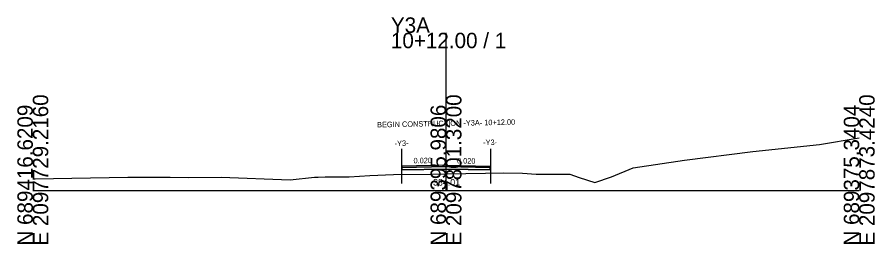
# Model space of a CAD drawing. Extents: x -26 to 2453, y -10 to 1032.
# Drawn here: x 1147.2 to 1302.8, y -9.7 to 31.5 of the extents above; entities that cross this region are included whole.
import ezdxf

# ---------------------------------------------------------------- set-up
doc = ezdxf.new("R2010")
doc.units = 0
for name, color, linetype in [('Exist Cross Section Cell', 7, 'Continuous'), ('Exist XS Center Line Elevation Label', 7, 'Continuous'), ('Exist XS Ground Line', 7, 'Continuous'), ('Prop CMT Pvmt Course 1', 7, 'Continuous'), ('Prop CMT Pvmt Course 2', 7, 'Continuous'), ('Prop CMT Pvmt Course 3', 7, 'Continuous'), ('Prop CMT Pvmt Surface', 7, 'Continuous'), ('Prop CMT Pvmt Surface Shoulder', 7, 'Continuous'), ('Prop CMT Shld Paved Course 1', 7, 'Continuous'), ('Prop CMT Shld Paved Course 2', 7, 'Continuous'), ('Prop CMT Shld Paved Course 3', 7, 'Continuous'), ('Prop CMT Subgrade Earthwork', 7, 'Continuous'), ('Prop XS SE Text', 7, 'Continuous')]:
    doc.layers.add(name, color=color, linetype=linetype)

msp = doc.modelspace()

# ---------------------------------------------------------------- linework, layer by layer
at = {"layer": 'Exist Cross Section Cell'}
for p, q in [((1225, 0), (1225, 28.68)), ((1150, 0), (1225, 0)), ((1225, 0), (1300, 0))]:
    msp.add_line(p, q, dxfattribs=at)
at = {"layer": 'Exist XS Center Line Elevation Label'}
for p, q in [((1216.9, 7.58), (1216.9, 4.45)), ((1233.1, 7.58), (1233.1, 4.45)), ((1216.9, 4.45), (1216.9, 1.31)), ((1233.1, 4.45), (1233.1, 1.31))]:
    msp.add_line(p, q, dxfattribs=at)
at = {"layer": 'Exist XS Ground Line'}
msp.add_lwpolyline([(1150, 2.1), (1150.44, 2.12), (1157.09, 2.26), (1167.25, 2.44), (1169.79, 2.42), (1174.96, 2.41), (1178.29, 2.4), (1184.17, 2.45), (1196.73, 1.97), (1201.13, 2.43), (1201.77, 2.44), (1203.07, 2.47), (1207.42, 2.52), (1211.15, 2.76), (1215.44, 2.89), (1222.42, 2.96), (1225, 3.01), (1232.19, 3.16), (1235.5, 3.2), (1238.91, 3.18), (1241.35, 3), (1247.5, 2.99), (1249.16, 2.35), (1252, 1.49), (1255.06, 2.51), (1258.96, 4.13), (1268.31, 5.52), (1280.68, 7.1), (1292.8, 8.39), (1300, 9.56)], dxfattribs=at)
at = {"layer": 'Prop CMT Pvmt Course 1'}
for points in [[(1225, 4.61), (1217, 4.45)], [(1217, 4.45), (1217, 4.2)], [(1217, 4.2), (1225, 4.36)], [(1225, 4.36), (1225, 4.61)], [(1225, 4.61), (1233, 4.45)], [(1225, 4.36), (1225, 4.61)], [(1225, 4.36), (1225, 4.61)], [(1233, 4.2), (1225, 4.36)], [(1233, 4.45), (1233, 4.2)]]:
    msp.add_lwpolyline(points, dxfattribs=at)
msp.add_lwpolyline([(1225, 4.36), (1225, 4.49), (1225, 4.49), (1225, 4.36)], close=True, dxfattribs=at)
msp.add_lwpolyline([(1225, 4.36), (1225, 4.49), (1225, 4.49), (1225, 4.36)], close=True, dxfattribs=at)
msp.add_lwpolyline([(1225, 4.36), (1225, 4.49), (1225, 4.49), (1225, 4.36)], close=True, dxfattribs=at)
msp.add_lwpolyline([(1225, 4.36), (1225, 4.49), (1225, 4.49), (1225, 4.36)], close=True, dxfattribs=at)
at = {"layer": 'Prop CMT Pvmt Course 2'}
for points in [[(1217, 4.2), (1225, 4.36)], [(1225, 4.36), (1217, 4.2)], [(1217, 4.2), (1217, 3.87)], [(1225, 4.03), (1225, 4.36)], [(1233, 4.2), (1225, 4.36)], [(1225, 4.03), (1225, 4.36)], [(1225, 4.36), (1233, 4.2)], [(1225, 4.03), (1225, 4.36)], [(1233, 4.2), (1233, 3.87)]]:
    msp.add_lwpolyline(points, dxfattribs=at)
at = {"layer": 'Prop CMT Pvmt Course 3'}
for points in [[(1225, 4.36), (1217, 4.2)], [(1217, 4.2), (1217, 3.74)], [(1217, 3.74), (1225, 3.9)], [(1225, 4.36), (1233, 4.2)], [(1225, 3.9), (1225, 4.36)], [(1225, 3.9), (1225, 4.36)], [(1233, 3.74), (1225, 3.9)], [(1233, 4.2), (1233, 3.74)]]:
    msp.add_lwpolyline(points, dxfattribs=at)
at = {"layer": 'Prop CMT Pvmt Surface'}
for points in [[(1225, 4.61), (1217, 4.45)], [(1225, 4.61), (1233, 4.45)]]:
    msp.add_lwpolyline(points, dxfattribs=at)
at = {"layer": 'Prop CMT Pvmt Surface Shoulder'}
for points in [[(1217, 4.45), (1216.9, 4.45)], [(1233, 4.45), (1233.1, 4.45)]]:
    msp.add_lwpolyline(points, dxfattribs=at)
at = {"layer": 'Prop CMT Shld Paved Course 1'}
for points in [[(1216.9, 4.2), (1217, 4.2)], [(1217, 4.2), (1217, 4.45)], [(1233, 4.2), (1233, 4.45)], [(1233.1, 4.2), (1233, 4.2)]]:
    msp.add_lwpolyline(points, dxfattribs=at)
at = {"layer": 'Prop CMT Shld Paved Course 2'}
for points in [[(1216.9, 4.2), (1217, 4.2)], [(1217, 3.87), (1217, 4.2)], [(1233.1, 4.2), (1233, 4.2)], [(1233, 3.87), (1233, 4.2)]]:
    msp.add_lwpolyline(points, dxfattribs=at)
at = {"layer": 'Prop CMT Shld Paved Course 3'}
for points in [[(1217, 4.2), (1216.9, 4.2)], [(1216.9, 3.74), (1217, 3.74)], [(1217, 3.74), (1217, 4.2)], [(1233, 4.2), (1233.1, 4.2)], [(1233, 3.74), (1233, 4.2)]]:
    msp.add_lwpolyline(points, dxfattribs=at)
at = {"layer": 'Prop CMT Subgrade Earthwork'}
for points in [[(1217, 3.74), (1216.9, 3.74)], [(1225, 3.9), (1217, 3.74)], [(1225, 3.9), (1233, 3.74)], [(1233, 3.74), (1233.1, 3.74)]]:
    msp.add_lwpolyline(points, dxfattribs=at)

# ---------------------------------------------------------------- texts
at = {"layer": 'Exist Cross Section Cell'}
for s, p in [('Y3A', (1215, 28.68)), ('10+12.00 / 1', (1215, 25.88))]:
    msp.add_text(s, height=2.8, dxfattribs=at).set_placement(p)
for s, p in [('E 2097729.2160', (1152.8, -10)), ('E 2097801.3200', (1227.8, -10)), ('E 2097873.4240', (1302.8, -10)), ('N 689416.6209', (1150, -10)), ('N 689395.9806', (1225, -10)), ('N 689375.3404', (1300, -10))]:
    msp.add_text(s, height=2.8, rotation=90, dxfattribs=at).set_placement(p)
at = {"layer": 'Exist XS Center Line Elevation Label'}
msp.add_text('384.01', height=1.2, dxfattribs=at).set_placement((1222.65, 0.91))
at = {"layer": 'Prop XS SE Text'}
for s, rotation, p in [('BEGIN CONSTRUCTION -Y3A- 10+12.00', 1.1458, (1212.49, 11.47)), ('-Y3-', 1.1458, (1215.68, 8.07)), ('-Y3-', 1.1458, (1231.75, 8.24)), ('0.020', 1.1458, (1219.11, 4.93)), ('0.020', 358.8542, (1226.99, 4.94))]:
    msp.add_text(s, height=1, rotation=rotation, dxfattribs=at).set_placement(p)

doc.saveas('drawing.dxf')
